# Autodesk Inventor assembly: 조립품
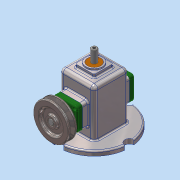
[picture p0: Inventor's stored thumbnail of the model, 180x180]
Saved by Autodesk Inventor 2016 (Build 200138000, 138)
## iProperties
Created: 2018-07
Part Number: 조립품
Material: 일반
Document SubType Name: Assembly
Designer: 605-17
Author: 605-17
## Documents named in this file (16)
- C:\480707V1014\조립품.iam
- C:\480707V1014\본체.ipt
- C:\480707V1014\뒤커버.ipt
- C:\480707V1014\앞커버.ipt
- C:\480707V1014\오일 실 12 25 7.ipt
- C:\480707V1014\베어링 12x32x10.ipt
- C:\480707V1014\고정핀 1.2x8.ipt
- C:\480707V1014\링크.ipt
- C:\480707V1014\슬라이드.ipt
- C:\480707V1014\핀 5x18.ipt
- C:\480707V1014\V벨트풀리.ipt
- C:\480707V1014\부시.ipt
- C:\480707V1014\편심축.ipt
- C:\480707V1014\키 4x4x10.ipt
- C:\480707V1014\멈춤나사 M3x8.ipt
- C:\480707V1014\볼트 M4.ipt
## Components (3 placed, 3 different names)
1. 고정핀 1.2x8:1 — 각도:3
2. 핀 5x18:1
3. V벨트풀리:1 — 각도:2
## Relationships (2: Angle 2)
- 각도:2 [Angle]: V벨트풀리:1
- 각도:3 [Angle]: 고정핀 1.2x8:1
